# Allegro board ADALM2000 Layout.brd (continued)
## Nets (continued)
GND: A1.5 A2.5 A2.7 A2.15 A4.5 A6.4(V-) A6.PAD A7.PAD A8.4(V-) A8.PAD A9.PAD A11.3 A13.4(V-) A13.PAD A14.3 C1.2(N2) C2.1 C3.2(N2) C4.2(N2) C5.2(N2) C6.2(N2) C7.2(N2) C8.2(N2) C9.2(N2) C10.2(N2) C11.2(N2) C12.2(N2) C13.2(N2) C14.2(N2) C16.2(N2) C17.2(N2) C18.2(N2) C19.2(N2) C20.2(N2) C21.2(N2) C22.2(N2) C23.2(N2) C24.1 C25.2(N2) C26.2(N2) C27.2(N2) C28.2(N2) C29.2(N2) C30.2(N2) C31.2(N2) C32.2(N2) C33.2(N2) C34.2(N2) C35.2(N2) C36.2(N2) C37.2(N2) C38.2(N2) C39.2(N2) C40.2(N2) C41.2(N2) C42.2(N2) C43.2(N2) C44.2(N2) C45.2(N2) C46.2(N2) C47.2(N2) C48.2(N2) C49.2(N2) C50.2(N2) C51.2(N2) C53.2(N2) C54.2(N2) C55.2(N2) C56.2(N2) C57.2(N2) C58.2(N2) C59.2(N2) C60.2(N2) C61.2(N2) C62.2(N2) C63.2(N2) C64.2(N2) C65.2(N2) C66.2(N2) C67.2(N2) C68.2(N2) C69.2(N2) C70.2(N2) C71.2(N2) C74.2(N2) C77.2(N2) C78.2(N2) C79.2(N2) C80.2(N2) C81.2(N2) C82.2(N2) C83.2(N2) C84.2(N2) C86.2(N2) C87.2(N2) C90.2(N2) C91.2(N2) C93.2(N2) C96.2(N2) C97.2(N2) C98.2(N2) C99.2(N2) C100.2(N2) C101.2(N2) C102.2(N2) C105.2(N2) C106.1 C107.2(N2) C108.1 C109.2(N2) C110.1 C111.2(N2) C112.1 C113.2(N2) C114.1 C115.2(N2) C116.1 C117.2(N2) C118.1 C119.2(N2) C120.1 C121.1 C123.2(N2) C124.2(N2) C125.2(N2) C126.2(N2) C127.2(N2) C128.2(N2) C131.2(N2) C133.1 C134.2(N2) C135.2(N2) C136.2(N2) C137.2(N2) C138.2(N2) C139.2(N2) C140.2(N2) C141.2(N2) C142.2(N2) C144.2(N2) C148.2(N2) C149.2(N2) C150.2(N2) C151.2(N2) C152.2(N2) C153.2(N2) C154.2(N2) C155.1 C156.2(N2) C157.1 C158.2(N2) C159.1 C160.2(N2) C161.1 C164.2(N2) C165.1 C166.2(N2) C167.1 C168.2(N2) C169.1 C170.2(N2) C171.1 C172.1 C174.2(N2) C175.2(N2) C176.2(N2) C177.2(N2) C178.2(N2) C179.2(N2) C180.2(N2) C182.2(N2) C183.2(N2) C185.2(N2) C186.2(N2) C187.2(N2) C190.2(N2) C191.2(N2) C192.2(N2) C193.1 C194.1 C195.2(N2) C196.2(N2) C197.2(N2) C198.2(N2) C199.2(N2) C202.2(N2) C204.2(N2) C205.2(N2) C206.2(N2) C207.2(N2) C208.2(N2) C209.2(N2) C210.2(N2) C211.2(N2) C212.2(N2) C213.2(N2) C214.2(N2) C215.2(N2) C216.1 C217.2(N2) C218.2(N2) C219.2(N2) C220.2(N2) C221.2(N2) C222.2(N2) C223.2(N2) C224.2(N2) C225.2(N2) C226.2(N2) C227.2(N2) C228.2(N2) C229.2(N2) C230.2(N2) C231.2(N2) C232.2(N2) C233.2(N2) C234.2(N2) C235.2(N2) C238.2(N2) C239.2(N2) C240.2(N2) C241.2(N2) C242.2(N2) C243.1 C244.2(N2) C245.1 C246.2(N2) C247.1 C248.2(N2) C249.2(N2) C250.2(N2) C251.1 C253.2(N2) C254.1 C256.2(N2) C257.2(N2) C258.2(N2) C259.1 C260.2(N2) C261.2(N2) C262.2(N2) C263.1 C264.2(N2) C265.1 C268.2(N2) C269.1 C270.2(N2) C271.1 C272.2(N2) C273.1 C274.2(N2) C275.1 C276.2(N2) C277.1 C278.2(N2) C279.2(N2) C282.2(N2) C283.1 C284.2(N2) C285.2(N2) C286.2(N2) C287.2(N2) C288.2(N2) C289.2(N2) C290.2(N2) C291.2(N2) C292.2(N2) C293.2(N2) C294.2(N2) C295.2(N2) C296.2(N2) C297.2(N2) C298.2(N2) C299.2(N2) C300.2(N2) C301.2(N2) C308.2(N2) C309.1 C310.2(N2) C311.2(N2) C314.2(N2) C315.1 C316.2(N2) C317.1 C318.2(N2) C319.1 C320.2(N2) C321.2(N2) C322.2(N2) C323.1 C324.2(N2) C327.2(N2) C328.2(N2) C329.2(N2) C330.2(N2) C331.2(N2) C332.2(N2) C333.2(N2) C334.2(N2) C335.2(N2) C336.2(N2) C338.2(N2) C340.2(N2) C579.2(N2) C588.2(N2) C589.2(N2) C595.2(N2) C596.2(N2) C597.2(N2) C598.2(N2) C599.2(N2) C600.2(N2) C607.2(N2) C614.2(N2) C615.2(N2) C616.2(N2) C617.2(N2) C618.2(N2) C626.2(N2) C633.2(N2) C637.2(N2) C639.2(N2) C641.2(N2) C643.2(N2) C644.2(N2) C645.2(N2) C647.2(N2) C648.1 C649.2(N2) C650.1 C651.2(N2) C652.2(N2) C654.2(N2) C655.2(N2) C656.2(N2) C657.2(N2) C658.2(N2) C659.2(N2) C660.2(N2) C662.2(N2) C663.2(N2) C664.2(N2) C665.2(N2) C666.2(N2) C667.2(N2) C668.2(N2) C669.2(N2) C670.2(N2) C671.2(N2) C672.2(N2) C673.2(N2) C674.2(N2) C675.2(N2) C676.2(N2) C678.2(N2) C679.2(N2) C680.2(N2) C683.2(N2) C686.2(N2) C692.1 C696.2(N2) C697.2(N2) C698.2(N2) C699.2(N2) C700.2(N2) C701.2(N2) C702.2(N2) C703.2(N2) C704.2(N2) C705.2(N2) C706.2(N2) C707.2(N2) C708.2(N2) C709.2(N2) C710.2(N2) C711.2(N2) C712.2(N2) C713.2(N2) C737.2(N2) C738.2(N2) C740.2(N2) C742.2(N2) C745.1 C746.1 C748.2(N2) C751.1 C753.1 C754.2(N2) C756.1 C758.2(N2) C761.2(N2) C762.2(N2) C769.2(N2) C774.2(N2) C788.2(N2) C789.2(N2) C790.2(N2) C792.2(N2) C793.2(N2) C795.1 C801.2(N2) C803.2(N2) C805.2(N2) C807.2(N2) D1.A(P) D2.1(P) D3.1(P) D4.1(P) D5.1(P) D6.1(P) D7.1(P) D8.1(P) D9.1(P) D10.1(P) D11.1(P) D12.1(P) D13.1(P) D14.1(P) D15.1(P) D16.1(P) D17.1(P) D18.1(P) D19.1(P) D26.C D739.A(P) D741.A(P) E687.1 GND_4.1(N1) GND_5.1(N1) GND_6.1(N1) GND_7.1(N1) GND_8.1(N1) GND_9.1(N1) GND_10.1(N1) L2.1 L10.3 L13.1 L14.1 P1.5 P1.6 P1.11 P1.12 P510.7 P510.9 Q2.2(S) Q3.1 Q4.1 Q5.1 Q8.2(S) Q9.2(S) Q512.2(S) R2.2(N2) R4.2(N2) R8.2(N2) R12.2(N2) R13.2(N2) R18.2(N2) R21.2(N2) R31.1 R43.2(N2) R46.2(N2) R57.1 R67.2(N2) R69.2(N2) R70.2(N2) R74.1 R75.1 R77.1 R80.2(N2) R82.2(N2) R83.1 R84.1 R85.1 R92.2(N2) R93.2(N2) R94.2(N2) R105.2(N2) R106.2(N2) R116.2(N2) R117.1 R120.2(N2) R121.1 R122.1 R123.1 R124.1 R138.2(N2) R141.2(N2) R154.2(N2) R158.1 R165.2(N2) R197.2(N2) R198.2(N2) R199.2(N2) R200.2(N2) R203.2(N2) R204.2(N2) R206.2(N2) R208.2(N2) R213.2(N2) R214.2(N2) R583.2(N2) R587.2(N2) R590.2(N2) R593.2(N2) R594.2(N2) R634.2(N2) R636.2(N2) R661.2(N2) R743.1 R747.2(N2) R760.1 R764.2(N2) R766.1 R800.2(N2) S1.3 S1.4 TP5.1(N1) TP6.1(N1) TP7.1(N1) U2.5 U2.11 U2.14 U2.19 U2.34 U2.62 U2.64 U2.PAD U6.1 U6.19 U6.20 U6.21 U6.22 U6.PAD U7.4 U7.8 U7.PAD U8.10 U8.12 U9.10 U9.12 U10.4 U10.10 U10.14 U10.15 U10.16 U10.PAD U11.8 U11.12 U12.4 U12.5 U12.PAD U13.6 U14.1 U14.3 U14.8 U14.11 U14.15 U14.22 U14.PAD U15.PAD U17.2 U18.1 U18.2 U19.1 U19.2 U20.3 U508.B3 U509.4 U509.8 U509.PAD U511.A1 U511.A11 U511.B8 U511.C5 U511.C15 U511.D2 U511.D12 U511.E5 U511.E7 U511.E8 U511.E9 U511.F10 U511.G3 U511.G5 U511.G13 U511.H6 U511.H8 U511.H10 U511.J5 U511.J9 U511.K4 U511.K7 U511.K10 U511.K14 U511.L1 U511.L5 U511.L11 U511.M8 U511.N5 U511.N15 U511.P2 U511.P12 U511.R9 U518.1 U518.19 U518.20 U518.21 U518.22 U518.PAD U524.PAD U646.A9 U646.B1 U646.B3 U646.B9 U646.D1 U646.D8 U646.E1 U646.E2 U646.E8 U646.F9 U646.G1 U646.G8 U646.G9 U646.J2 U646.J8 U646.M1 U646.M9 U646.P1 U646.P9 U646.T1 U646.T9 VR1.1 Y1.2 Y523.2 Y578.2
PGND: C280.2(N2) C281.2(N2) C312.2(N2) C313.2(N2) C325.2(N2) C326.2(N2) L10.4(N4) P516.5 P519.5 R190.2(N2) R191.1 R192.2(N2) R744.2(N2) R749.2(N2) U16.B2 U21.PAD
VCCPINT: C279.1 C663.1 C665.1 C667.1 C669.1 C670.1 C671.1 C672.1 C673.1 C674.1 E26.2(N2) U511.E10 U511.F9 U511.G6 U511.G10 U511.H5 U511.J10 U511.K5 U511.L10 VCCPINT.1(N1)
VCCPLL: C680.1 C686.1 E677.2(N2) U511.F5(VCCPLL)
VIN: C4.1 C178.1 C183.1 C187.1 C190.1 C320.1 C321.1 C648.2(N2) C737.1 C738.1 C740.1 C742.1 DS11.A(P) DS12.A(P) E4.1 L10.2 R3.1 R88.1 R517.1 R638.1 R640.1 R750.2(N2) U6.14 U6.15 U6.16(VIN6) U6.25 U6.26 U6.27 U509.10 U518.14 U518.15 U518.16(VIN6) U518.25 U518.26 U518.27 VIN.1(N1)
VIN_5V_USB_DATA: C325.1 F1.2(N2) P516.1 R156.2(N2) U21.7 U21.8
VIN_5V_USB_POWER: C326.1 P519.1 R166.1 U16.A1 U21.1 U21.2
20MHZ_REFCLK: C52.2(N2) U14.16
AD9963_CSN: U2.17 U511.E11
AD9963_RESETN: R14.2(N2) U2.15 U511.E12
ADC_SC1_N: C122.2(N2) C123.1 D21.3 R38.2(N2) U2.4
ADC_SC1_P: C121.2(N2) C122.1 D20.3 R37.2(N2) U2.3
ADC_SC2_N: C172.2(N2) C173.1 D22.3 R63.2(N2) U2.12
ADC_SC2_P: C173.2(N2) C174.1 D23.3 R64.2(N2) U2.13
ADF4360_CS: U14.19 U511.G15
ADF4360_LD: U14.23 U15.10
ADP2114_VIN_1: C748.1 R517.2(N2) U518.4 U518.8 U518.10 U518.31
ADP2114_VIN_2: C196.1 R88.2(N2) R89.1 R91.2(N2) R149.2(N2) U6.4 U6.8 U6.28
AWG1_PD: A7.1 Q8.3 R201.2(N2)
AWG2_PD: A9.1 Q9.3 R202.2(N2)
CALIB_REFERENCE1: C219.1 CALIB_REF1.1(N1) R79.2(N2) R80.1 U8.4 U9.4
CALIB_REFERENCE2: C220.1 CALIB_REF2.1(N1) R81.2(N2) R82.1 U8.9 U9.9
COMP_1P35V: C756.2(N2) C757.1 U518.7
COMP_1V0_D: C197.1 R90.1 U6.2
COMP_1V8: C751.2(N2) R752.1 U518.2
COMP_3V3_D: C199.1 C203.1 U6.7
DAC_AVG1_N: A10.2 C252.1 R95.1 U2.66
DAC_AVG1_P: A10.3 C248.1 R93.1 U2.65
DAC_AVG2_N: A10.6 C255.1 R96.1 U2.59
DAC_AVG2_P: A10.5 C249.1 R94.1 U2.60
DAC_OFFSET_SC1: A6.3 U11.5
DAC_OFFSET_SC2: A6.5 U11.10
DAC_USR_POW_NEG: R151.2(N2) R153.1 R159.1
DAC_USR_POW_NEG_9963: R153.2(N2) U2.69
DAC_USR_POW_POS: A12.3 R150.2(N2) R152.1
DAC_USR_POW_POS_9963: R152.2(N2) U2.68
DDR3_A0: R601.1 U511.P1 U646.N3
DDR3_A1: R608.1 U511.N1 U646.P7
DDR3_A2: R602.1 U511.M1 U646.P3
DDR3_A3: R609.1 U511.M4 U646.N2
DDR3_A4: R603.1 U511.P3 U646.P8
DDR3_A5: R610.1 U511.P4 U646.P2
DDR3_A6: R604.1 U511.P5 U646.R8
DDR3_A7: R611.1 U511.M5 U646.R2
DDR3_A8: R605.1 U511.P6 U646.T8
DDR3_A9: R612.1 U511.N4 U646.R3
DDR3_A10: R606.1 U511.J1 U646.L7
DDR3_A11: R613.1 U511.L2 U646.R7
DDR3_A12: R620.1 U511.M2 U646.N7
DDR3_A13: R627.1 U511.K2 U646.T3
DDR3_A14: R619.1 U511.K1 U646.T7
DDR3_BA0: R628.1 U511.M6 U646.M2
DDR3_BA1: R621.1 U511.R1 U646.N8
DDR3_BA2: R629.1 U511.N6 U646.M3
DDR3_CAS#: R623.1 U511.R5 U646.K3
DDR3_CK_N: R625.2(N2) U511.N2 U646.K7
DDR3_CK_P: R625.1 U511.N3 U646.J7
DDR3_CKE: R631.1 U511.L3 U646.K9
DDR3_CS#: R632.1 U511.R2 U646.L2
DDR3_DM0: U511.B1 U646.E7
DDR3_DM1: U511.D3 U646.D3
DDR3_DQ0: U511.D4 U646.E3
DDR3_DQ1: U511.A2 U646.F7
DDR3_DQ2: U511.C4 U646.F2
DDR3_DQ3: U511.C1 U646.F8
DDR3_DQ4: U511.B4 U646.H3
DDR3_DQ5: U511.A4 U646.H8
DDR3_DQ6: U511.C3 U646.G2
DDR3_DQ7: U511.A3 U646.H7
DDR3_DQ8: U511.E1 U646.D7
DDR3_DQ9: U511.D1 U646.C3
DDR3_DQ10: U511.E2 U646.C8
DDR3_DQ11: U511.E3 U646.C2
DDR3_DQ12: U511.F3 U646.A7
DDR3_DQ13: U511.G1 U646.A2
DDR3_DQ14: U511.H1 U646.B8
DDR3_DQ15: U511.H2 U646.A3
DDR3_DQS0_N: U511.B2 U646.G3
DDR3_DQS0_P: U511.C2 U646.F3
DDR3_DQS1_N: U511.F2 U646.B7
DDR3_DQS1_P: U511.G2 U646.C7
DDR3_ODT: R624.1 U511.K3 U646.K1
DDR3_RAS#: R630.1 U511.R6 U646.J3
DDR3_RST#: R636.1 U511.L4 U646.T2
DDR3_WE#: R622.1 U511.R3 U646.L3
DIO_0: D18.3 RT11.2(N2) U511.K11
DIO_1: D17.3 RT12.2(N2) U511.K12
DIO_2: D16.3 RT13.2(N2) U511.K13
DIO_3: D15.3 RT14.2(N2) U511.L13
DIO_4: D14.3 RT15.2(N2) U511.L14
DIO_5: D13.3 RT16.2(N2) U511.M14
DIO_6: D12.3 RT17.2(N2) U511.L15
DIO_7: D11.3 RT18.2(N2) U511.M15
DIO_8: D3.3 RT2.1 U511.N13
DIO_9: D4.3 RT3.1 U511.P14
DIO_10: D5.3 RT4.1 U511.R12
DIO_11: D6.3 RT5.1 U511.R13
DIO_12: D7.3 RT6.1 U511.P11
DIO_13: D8.3 RT7.1 U511.R11
DIO_14: D9.3 RT8.1 U511.P15
DIO_15: D10.3 RT9.1 U511.R15
DONE_LED_OVERRIDE: Q1.1 R130.2(N2) U15.4
EN_AWG1: Q8.1 R199.1 U15.16
EN_AWG2: Q9.1 R200.1 U15.15
EN_DAT_USB: R189.2(N2) R190.1 U21.6
EN_POW_USB: R166.2(N2) R189.1 U21.3
EN_SC: Q3.2(S) R154.1 U15.3 U17.3(SHDN_N) VR1.4(SHDN_N)
EN_SC1_CAL2: A2.8 U15.7
EN_SC1_HG: A4.1 A4.9 U15.12
EN_SC1_LG: A4.8 A4.16 U15.11
EN_SC2_CAL2: A2.16 U15.8
EN_SC2_HG: A1.1 A1.9 U15.14
EN_SC2_LG: A1.8 A1.16 U15.13
EN_SC_CAL1: A2.1 A2.9 U15.9
EN_USR_POW_NEG: Q5.2(S) U15.2
EN_USR_POW_POS: Q4.2(S) U15.1
ENABLE_POW_NEG: A14.5 Q5.3 R147.1
ENABLE_POW_POS: A12.5 Q4.3 R129.1
FB_1V0_D: R207.2(N2) R208.1 U6.32
FB_1V8: R765.1 R766.2(N2) U518.32
FB_1V35: R763.2(N2) R764.1 U518.9
FB_3V3_D: R205.2(N2) R206.1 U6.9
IN_SC1_N: C72.1 P1.1 R16.1
IN_SC1_P: C75.1 P1.2 R19.1
IN_SC2_N: C129.1 P1.3 R41.1
IN_SC2_P: C132.1 P1.4 R44.1
JTAG_TCK: P510.4 TCK.1(N1) U511.G9
JTAG_TDI: P510.8 TDI.1(N1) U511.L7
JTAG_TDO: P510.6 TDO.1(N1) U511.L8
JTAG_TMS: P510.2 TMS.1(N1) U511.L9
LOOP_FILT: C223.1 R6.1 R86.1 U14.24
MASTER_CLK_N: C237.2(N2) U2.56
MASTER_CLK_P: C236.2(N2) U2.57
MUX_EN: R47.2(N2) U8.16 U9.16
OFFSET_AWG1: R99.1 U11.4
OFFSET_AWG2: R100.1 U11.11
OFFSET_SC1: A6.1 C304.2(N2) OFF_SC1.1(N1) R29.1 R127.2(N2)
OFFSET_SC2: A6.7 C305.2(N2) OFF_SC2.1(N1) R54.1 R128.2(N2)
OUT_AWG1: P1.10 R132.2(N2) R135.1
OUT_AWG1_CALIB: R135.2(N2) R197.1 U8.3
OUT_AWG2: P1.9 R133.2(N2) R134.1
OUT_AWG2_CALIB: R134.2(N2) R198.1 U9.3
PG_1P0V: R89.2(N2) U6.29 U518.28
PG_1P8V: R750.1 U6.13 U7.3 U10.6 U12.3 U518.13 U518.29
PS-SRST#: R791.2(N2) U508.A4 U511.B11
PS_MIO01_500_QSPI0_SS_B: R586.2(N2) U508.C2 U511.A5
PS_MIO02_500_QSPI0_IO0: R593.1 U508.D3 U511.A8
PS_MIO03_500_QSPI0_IO1: R594.1 U508.D2 U511.A7
PS_MIO04_500_QSPI0_IO2: R590.1 U508.C4(W#DQ2) U511.C8
PS_MIO05_500_QSPI0_IO3: IO3.1(N1) P510.5 R591.1 U508.D4 U511.A9
PS_MIO06_500_QSPI0_SCLK: R583.1 U508.B2 U511.A10
PS_MIO07_500_USB_RESET_B: R798.2(N2) U511.A12 U524.27
PS_MIO28_501_USB0_D4: U511.A15 U524.7
PS_MIO29_501_USB0_DIR: U511.D11 U524.31
PS_MIO30_501_USB0_STP: U511.B15 U524.29
PS_MIO31_501_USB0_NXT: U511.C12 U524.2
PS_MIO32_501_USB0_D0: U511.E15 U524.3
PS_MIO33_501_USB0_D1: U511.C11 U524.4
PS_MIO34_501_USB0_D2: U511.D15 U524.5
PS_MIO35_501_USB0_D3: U511.A14 U524.6
PS_MIO36_501_USB0_CLK: U511.B14 U524.1
PS_MIO37_501_USB0_D5: U511.C14 U524.9
PS_MIO38_501_USB0_D6: U511.A13 U524.10
PS_MIO39_501_USB0_D7: U511.D14 U524.13
PWR_GD_1.35V: C588.1 R585.2(N2) R587.1 U511.C9 U518.12
PWR_GOOD: R155.2(N2) U6.12 U7.6 U10.3 U15.19
REF_1V0_AWG: C62.1 R143.2(N2) U2.63
REF_1V2: A8.3 A8.5 A13.3 A13.5 C97.1 C291.1 C293.1 C296.1 U11.7(VREF) U19.5(VOUT_SENSE) U19.6 U20.10(VREFIN)
REF_1V2_SC: C289.1 C292.1 R79.1 R81.1 R115.1 U18.5(VOUT_SENSE) U18.6
REF_AWG1: A13.1 A13.2 R97.1
REF_AWG2: A13.6 A13.7 R98.1
REF_SC1: A8.7 C302.2(N2) R28.1 R125.2(N2)
REF_SC2: A8.1 C303.2(N2) R55.1 R126.2(N2)
RX_CLK: R173.1 U511.N11
RXCML: C65.1 R36.2(N2) R62.2(N2) U2.10
RXD_0: R188.2(N2) U511.P10
RXD_1: R187.2(N2) U511.R10
RXD_2: R186.2(N2) U511.P8
RXD_3: R185.2(N2) U511.P9
RXD_4: R184.2(N2) U511.N7
RXD_5: R183.2(N2) U511.N8
RXD_6: R182.2(N2) U511.M10
RXD_7: R181.2(N2) U511.M11
RXD_8: R180.2(N2) U511.R7
RXD_9: R179.2(N2) U511.R8
RXD_10: R178.2(N2) U511.M9
RXD_11: R177.2(N2) U511.N9
RXIQ: R176.2(N2) U511.P13
SC_CAL_MUX0: U8.15 U9.15 U15.6
SC_CAL_MUX1: U8.14 U9.14 U15.5
SC_PD: Q3.3 R131.1 U3.14 U3.20 U4.14 U4.20
SCL: R211.2(N2) U11.14 U15.23 U20.7 U511.F14
SCLK: U2.16 U14.17 U511.E13
SDA: R210.2(N2) U11.13 U15.22 U20.8 U511.F13
SDIO: U2.18 U14.18 U511.F12
STAT_DATA: R196.2(N2) U15.21 U21.11
STAT_POWER: R195.2(N2) U15.20 U21.14
SUPPLY_NEG: C308.1 P1.7 R139.1 R160.2(N2) R163.2(N2)
SUPPLY_NEG_MONITOR: A11.1 R136.2(N2) U2.71
SUPPLY_POS: C297.1 P1.8 R137.1 R161.2(N2) R162.2(N2)
SUPPLY_POS_MONITOR: R137.2(N2) R138.1 U2.70
TRIG_1: D19.3 RT10.2(N2) U511.M12
TRIG_2: D2.3 RT1.1 U511.N12
TX_CLK: R174.2(N2) U511.L12
TXD_0: R171.1 U511.H12
TXD_1: R172.1 U511.G11
TXD_2: R170.1 U511.H13
TXD_3: R169.1 U511.G12
TXD_4: R168.1 U511.H14
TXD_5: R167.1 R217.2(N2) U511.G14
TXD_6: R114.1 U511.K15
TXD_7: R113.1 U511.J15
TXD_8: R112.1 U511.J14
TXD_9: R109.1 U511.J13
TXD_10: R111.1 U511.J11
TXD_11: R110.1 U511.H11
TXIQ: R175.2(N2) U511.N14
UART_RX: P510.1 RX.1(N1) U511.C6
UART_TX: P510.3 TX.1(N1) U511.B7
UNNAMED_16_ADP5074_I189_COMP: C182.1 R1.2(N2) U10.7
UNNAMED_16_ADP5074_I189_FB: R7.2(N2) R10.1 U10.8
UNNAMED_16_ADP5074_I189_SLEW: R8.1 U10.2
UNNAMED_16_ADP5074_I189_SS: R2.1 U10.5
UNNAMED_16_ADP5074_I189_SW: D24.C L2.2(N2) U10.1
UNNAMED_16_ADP5074_I189_VREF: C6.1 R7.1 U10.9
UNNAMED_16_ADP5074_I189_VREG: C3.1 U10.11(VREG)
UNNAMED_16_ADP7182V2_I221_ADJ: R77.2(N2) R78.1 U13.3
UNNAMED_16_ADP7182V2_I221_VOUT: C218.1 E19.1 R78.2(N2) U13.1 U13.2(VOUT1)
UNNAMED_16_CAP_I180_N1: C1.1 R1.1
UNNAMED_16_CAP_I199_N1: C8.1 D24.A(P) L4.1 R9.1
UNNAMED_16_CAP_I236_N1: C328.1 VR1.3
UNNAMED_29_CN30PODDEVENV2_I44_1: P1.16 RT11.1
UNNAMED_29_CN30PODDEVENV2_I44_2: P1.18(N9) RT12.1
UNNAMED_29_CN30PODDEVENV2_I44_3: P1.20 RT13.1
UNNAMED_29_CN30PODDEVENV2_I44_4: P1.22 RT14.1
UNNAMED_29_CN30PODDEVENV2_I44_5: P1.24 RT15.1
UNNAMED_29_CN30PODDEVENV2_I44_6: P1.26 RT16.1
UNNAMED_29_CN30PODDEVENV2_I44_7: P1.28 RT17.1
UNNAMED_29_CN30PODDEVENV2_I44_8: P1.30 RT18.1
UNNAMED_29_CN30PODDEVENV2_I44_N: P1.14 RT10.1
UNNAMED_29_CN30PODDEVENV2_I45_1: P1.15 RT2.2(N2)
UNNAMED_29_CN30PODDEVENV2_I45_2: P1.17 RT3.2(N2)
UNNAMED_29_CN30PODDEVENV2_I45_3: P1.19 RT4.2(N2)
UNNAMED_29_CN30PODDEVENV2_I45_4: P1.21 RT5.2(N2)
UNNAMED_29_CN30PODDEVENV2_I45_5: P1.23 RT6.2(N2)
UNNAMED_29_CN30PODDEVENV2_I45_6: P1.25 RT7.2(N2)
UNNAMED_29_CN30PODDEVENV2_I45_7: P1.27 RT8.2(N2)
UNNAMED_29_CN30PODDEVENV2_I45_8: P1.29 RT9.2(N2)
UNNAMED_29_CN30PODDEVENV2_I45_N: P1.13 RT1.2(N2)
UNNAMED_30_AD9963_I47_AUXADCREF: C63.1 U2.2
UNNAMED_30_AD9963_I47_AUXIN1: R3.2(N2) R4.1 U2.72
UNNAMED_30_AD9963_I47_DLLFILT: C64.1 R15.1 U2.54
UNNAMED_30_AD9963_I47_RXBIAS: R13.1 U2.6
UNNAMED_30_AD9963_I47_TRXCLK: R173.2(N2) U2.36
UNNAMED_30_AD9963_I47_TRXD0: R188.1 U2.32
UNNAMED_30_AD9963_I47_TRXD1: R187.1 U2.31
UNNAMED_30_AD9963_I47_TRXD2: R186.1 U2.30
UNNAMED_30_AD9963_I47_TRXD3: R185.1 U2.29
UNNAMED_30_AD9963_I47_TRXD4: R184.1 U2.28
UNNAMED_30_AD9963_I47_TRXD5: R183.1 U2.27
UNNAMED_30_AD9963_I47_TRXD6: R182.1 U2.26
UNNAMED_30_AD9963_I47_TRXD7: R181.1 U2.25
UNNAMED_30_AD9963_I47_TRXD8: R180.1 U2.24
UNNAMED_30_AD9963_I47_TRXD9: R179.1 U2.23
UNNAMED_30_AD9963_I47_TRXD10: R178.1 U2.22
UNNAMED_30_AD9963_I47_TRXD11: R177.1 U2.21
UNNAMED_30_AD9963_I47_TRXIQ: R176.1 U2.35
UNNAMED_30_AD9963_I47_TXCLK: R174.1 U2.37
UNNAMED_30_AD9963_I47_TXD0: R171.2(N2) U2.50
UNNAMED_30_AD9963_I47_TXD1: R172.2(N2) U2.49
UNNAMED_30_AD9963_I47_TXD2: R170.2(N2) U2.48
UNNAMED_30_AD9963_I47_TXD3: R169.2(N2) U2.47
UNNAMED_30_AD9963_I47_TXD4: R168.2(N2) U2.46
UNNAMED_30_AD9963_I47_TXD5: R167.2(N2) U2.45
UNNAMED_30_AD9963_I47_TXD6: R114.2(N2) U2.44
UNNAMED_30_AD9963_I47_TXD7: R113.2(N2) U2.43
UNNAMED_30_AD9963_I47_TXD8: R112.2(N2) U2.42
UNNAMED_30_AD9963_I47_TXD9: R109.2(N2) U2.41
UNNAMED_30_AD9963_I47_TXD10: R111.2(N2) U2.40
UNNAMED_30_AD9963_I47_TXD11: R110.2(N2) U2.39
UNNAMED_30_AD9963_I47_TXIQ: R175.1 U2.38
UNNAMED_30_CAP_I112_N1: C66.1 R15.2(N2)
UNNAMED_31_AD8066_I6_INV: A3.2 C89.1 R24.1
UNNAMED_31_AD8066_I6_NINV: A3.3 C85.2(N2) R22.2(N2)
UNNAMED_31_AD8066_I6_OUT: A3.1 C89.2(N2) R24.2(N2) R26.1
UNNAMED_31_AD8066_I55_INV: A3.6 C92.1 R25.1
UNNAMED_31_AD8066_I55_NINV: A3.5 C88.2(N2) R23.2(N2)
UNNAMED_31_AD8066_I55_OUT: A3.7(OUT) C92.2(N2) R25.2(N2) R27.1
UNNAMED_31_ADA49402V2_I232_: C103.2(N2) R34.2(N2) U3.23
UNNAMED_31_ADA49402V2_I232__1: C104.1 R27.2(N2) R28.2(N2) R35.1 U3.1
UNNAMED_31_ADA49402V2_I232__2: C104.2(N2) R35.2(N2) U3.2
UNNAMED_31_ADA49402V2_I232__3: C103.1 R26.2(N2) R29.2(N2) R34.1 U3.24
UNNAMED_31_ADA49402V2_I232__4: R37.1 U3.19
UNNAMED_31_ADA49402V2_I232__5: R38.1 U3.18
UNNAMED_31_ADA49402V2_I232_VOCM: R36.1 U3.11 U3.17
UNNAMED_31_ADA49402V2_I233_: R33.2(N2) U3.8
UNNAMED_31_ADA49402V2_I233__1: R39.1 U3.13
UNNAMED_31_ADA49402V2_I233__2: R40.1 U3.12
UNNAMED_31_ADA49402V2_I233__3: R32.2(N2) U3.5
UNNAMED_31_ADA49402V2_I233__4: R31.2(N2) R33.1 U3.7
UNNAMED_31_ADA49402V2_I233__5: R30.2(N2) R32.1 U3.6
UNNAMED_31_ADG202N_I1_D: A2.6 A4.10 A4.15 C88.1 R23.1
UNNAMED_31_ADG202N_I1_S: A4.14 C73.2(N2) C74.1 C181.2(N2) C185.1 R17.2(N2) R18.1
UNNAMED_31_ADG202N_I2_S: A4.11 C69.1 C72.2(N2) C73.1 C181.1 R16.2(N2) R17.1
UNNAMED_31_ADG202N_I19_D: A2.3 A4.2 A4.7 C85.1 R22.1
UNNAMED_31_ADG202N_I19_S: A4.3 C71.1 C75.2(N2) C76.1 C189.1 R19.2(N2) R20.1
UNNAMED_31_ADG202N_I20_S: A4.6 C76.2(N2) C77.1 C189.2(N2) C336.1 R20.2(N2) R21.1
UNNAMED_31_ADG1404V2_I235_D: A2.2 U8.6
UNNAMED_31_DIO3PV3_I80_N: D20.2 D21.2 R40.2(N2)
UNNAMED_31_DIO3PV3_I80_P: D20.1(P) D21.1(P) R39.2(N2)
UNNAMED_32_AD8066_I42_INV: A5.6 C146.1 R50.1
UNNAMED_32_AD8066_I42_NINV: A5.5 C143.2(N2) R48.2(N2)
UNNAMED_32_AD8066_I42_OUT: A5.7(OUT) C146.2(N2) R50.2(N2) R53.1
UNNAMED_32_AD8066_I82_INV: A5.2 C147.1 R51.1
UNNAMED_32_AD8066_I82_NINV: A5.3 C145.2(N2) R49.2(N2)
UNNAMED_32_AD8066_I82_OUT: A5.1 C147.2(N2) R51.2(N2) R52.1
UNNAMED_32_ADA49402V2_I190_: C163.2(N2) R61.2(N2) U4.2
UNNAMED_32_ADA49402V2_I190__1: C162.1 R52.2(N2) R55.2(N2) R60.1 U4.24
UNNAMED_32_ADA49402V2_I190__2: C163.1 R53.2(N2) R54.2(N2) R61.1 U4.1
UNNAMED_32_ADA49402V2_I190__3: C162.2(N2) R60.2(N2) U4.23
UNNAMED_32_ADA49402V2_I190__4: R63.1 U4.19
UNNAMED_32_ADA49402V2_I190__5: R64.1 U4.18
UNNAMED_32_ADA49402V2_I190_VOCM: R62.1 U4.11 U4.17
UNNAMED_32_ADA49402V2_I191_: R59.2(N2) U4.8
UNNAMED_32_ADA49402V2_I191__1: R66.1 U4.12
UNNAMED_32_ADA49402V2_I191__2: R65.1 U4.13
UNNAMED_32_ADA49402V2_I191__3: R58.2(N2) U4.5
UNNAMED_32_ADA49402V2_I191__4: R57.2(N2) R59.1 U4.7
UNNAMED_32_ADA49402V2_I191__5: R56.2(N2) R58.1 U4.6
UNNAMED_32_ADG202N_I18_S: A1.14 C130.2(N2) C134.1 C339.2(N2) C340.1 R45.2(N2) R46.1
UNNAMED_32_ADG202N_I25_S: A1.11 C128.1 C130.1 C132.2(N2) C339.1 R44.2(N2) R45.1
UNNAMED_32_ADG202N_I26_S: A1.6 C95.2(N2) C131.1 C337.2(N2) C338.1 R42.2(N2) R43.1
UNNAMED_32_ADG202N_I34_S: A1.3 C95.1 C126.1 C129.2(N2) C337.1 R41.2(N2) R42.1
UNNAMED_32_ADG202N_I163_S: A1.2 A1.7 A2.14 C145.1 R49.1
UNNAMED_32_ADG202N_I164_S: A1.10 A1.15 A2.11 C143.1 R48.1
UNNAMED_32_ADG1404V2_I201_D: A2.10 U9.6
UNNAMED_32_DIO3PV3_I76_N: D22.2 D23.2 R66.2(N2)
UNNAMED_32_DIO3PV3_I76_P: D22.1(P) D23.1(P) R65.2(N2)
UNNAMED_33_AD8000_I139_FB: A7.2 R107.2(N2) R194.2(N2)
UNNAMED_33_AD8000_I139_INV: A7.3 C266.1 R101.2(N2) R102.2(N2) R107.1
UNNAMED_33_AD8000_I139_NINV: A7.4 C260.1 R99.2(N2) R105.1
UNNAMED_33_AD8000_I139_OUT: A7.7 R132.1
UNNAMED_33_AD8000_I141_FB: A9.2 R108.2(N2) R193.2(N2)
UNNAMED_33_AD8000_I141_INV: A9.3 C267.1 R103.2(N2) R104.2(N2) R108.1
UNNAMED_33_AD8000_I141_NINV: A9.4 C261.1 R100.2(N2) R106.1
UNNAMED_33_AD8000_I141_OUT: A9.7 R133.1
UNNAMED_33_ADOPAMP2_I1_OUT: A10.1 C252.2(N2) R95.2(N2) R102.1
UNNAMED_33_ADOPAMP2_I101_OUT: A10.7 C255.2(N2) R96.2(N2) R104.1
UNNAMED_33_CAP_I33_N1: C256.1 R97.2(N2) R101.1
UNNAMED_33_CAP_I95_N1: C257.1 R98.2(N2) R103.1
UNNAMED_33_CAP_I123_N2: C267.2(N2) R193.1
UNNAMED_33_CAP_I124_N2: C266.2(N2) R194.1
UNNAMED_34_AD56X5_I239_ADDR1: R119.2(N2) R120.1 U11.2
UNNAMED_34_AD56X5_I239_CLRN: R144.2(N2) U11.1 U11.6 U11.9
UNNAMED_34_AD56X7_I238_ADDR: R140.2(N2) R141.1 U20.6
UNNAMED_34_AD56X7_I238_CLRN: R142.2(N2) U20.4 U20.5
UNNAMED_34_AD56X7_I238_VOUTA: R150.1 U20.1
UNNAMED_34_AD56X7_I238_VOUTB: R151.1 U20.2
UNNAMED_34_AD8657V2_I252_: A6.2 C304.1 R123.2(N2) R127.1
UNNAMED_34_AD8657V2_I253_: A8.6 C302.1 R121.2(N2) R125.1
UNNAMED_34_AD8657V2_I254_: A8.2 C303.1 R122.2(N2) R126.1
UNNAMED_34_AD8657V2_I255_: A6.6 C305.1 R124.2(N2) R128.1
UNNAMED_34_AD8657V2_I284_: A11.6 C94.1 R117.2(N2) R118.1
UNNAMED_34_AD8657V2_I284__1: A11.5 C56.1 R115.2(N2) R116.1
UNNAMED_34_AD8657V2_I284_OUT: A11.7 C94.2(N2) R118.2(N2) R143.1
UNNAMED_35_AD8657V2_I160_: A11.2 R136.1 R139.2(N2)
UNNAMED_35_ADA48051_I114_: A14.4 C200.1 R159.2(N2) R160.1
UNNAMED_35_ADA48051_I114_VOUT: A14.1(VOUT) C179.1 C200.2(N2) D26.A(P) R163.1
UNNAMED_35_ADA48051_I125_: A12.4 C201.1 R158.2(N2) R161.1
UNNAMED_35_ADA48051_I125_VOUT: A12.1(VOUT) C175.1 C201.2(N2) D1.C R162.1
UNNAMED_35_CAP_I76_N2: C306.2(N2) C307.1
UNNAMED_36_ADF43609_I40_CC: C227.1 U14.12
UNNAMED_36_ADF43609_I40_CN: C230.1 U14.14
UNNAMED_36_ADF43609_I40_L1: L13.2(N2) R83.2(N2) U14.9
UNNAMED_36_ADF43609_I40_L2: L14.2(N2) R84.2(N2) U14.10
UNNAMED_36_ADF43609_I40_RFOUTA: C236.1 L15.1 U14.4
UNNAMED_36_ADF43609_I40_RFOUTB: C237.1 L16.1 U14.5
UNNAMED_36_ADF43609_I40_RSET: R85.2(N2) U14.13
UNNAMED_36_CAP_I47_N1: C52.1 Y1.3
UNNAMED_36_CAP_I53_N1: C238.1 R6.2(N2)
UNNAMED_37_ADP237X_I231_FB: C184.1 R70.1 R72.1 U7.5
UNNAMED_37_ADP237X_I231_SW: L3.1 U7.7
UNNAMED_37_ADP1614_I262_CLRES: R11.2(N2) R12.1 U12.9
UNNAMED_37_ADP1614_I262_COMP: C15.1 C17.1 U12.1
UNNAMED_37_ADP1614_I262_FB: R69.1 R73.1 U12.2
UNNAMED_37_ADP1614_I262_SS: C13.1 U12.10
UNNAMED_37_ADP1614_I262_SW1: D25.A(P) L6.2(N2) U12.6 U12.7
UNNAMED_37_ADP1614_I262_VIN: C16.1 R11.1 R68.1 U12.8(VIN)
UNNAMED_37_CAP_I212_N1: C191.1 C192.1 C195.1 C198.1 E8.1 L5.2(N2) R71.2(N2)
UNNAMED_37_CAP_I222_N1: C184.2(N2) C188.1 R71.1 R72.2(N2)
UNNAMED_37_CAP_I222_N2: C186.1 C188.2(N2) L3.2(N2) L5.1
UNNAMED_37_CAP_I260_N2: C15.2(N2) R67.1
UNNAMED_37_CAP_I315_N1: C23.1 D25.C L7.1
UNNAMED_37_LINLT1761_I320_ADJ: R164.2(N2) R165.1 U17.4
UNNAMED_38_ADP2114_I358_FREQ: R743.2(N2) U518.3
UNNAMED_38_ADP2114_I358_OPCFG: R747.1 U518.6
UNNAMED_38_ADP2114_I358_SS1: C745.2(N2) U518.30
UNNAMED_38_ADP2114_I358_SS2: C746.2(N2) U518.11
UNNAMED_38_ADP2114_I358_SW1: L521.1 U518.23 U518.24
UNNAMED_38_ADP2114_I358_SW3: L520.1 U518.17 U518.18
UNNAMED_38_ADP2114_I447_FREQ: R74.2(N2) U6.3
UNNAMED_38_ADP2114_I447_OPCFG: R75.2(N2) U6.6
UNNAMED_38_ADP2114_I447_SS1: C193.2(N2) U6.30
UNNAMED_38_ADP2114_I447_SS2: C194.2(N2) U6.11
UNNAMED_38_ADP2114_I447_SW1: L9.1 U6.23 U6.24
UNNAMED_38_ADP2114_I447_SW3: L8.1 U6.17 U6.18
UNNAMED_38_ADP2114_I447_V1SET: R91.1 R92.1 U6.31
UNNAMED_38_ADP2114_I447_V2SET: R149.1 R203.1 U6.10
UNNAMED_38_CAP_I366_N2: C757.2(N2) R760.2(N2)
UNNAMED_38_CAP_I379_N1: C761.1 C762.1 E768.1 L521.2(N2) R765.2(N2)
UNNAMED_38_CAP_I387_N2: C753.2(N2) R752.2(N2)
UNNAMED_38_CAP_I457_N1: C215.1 E21.1 L8.2(N2) R205.1
UNNAMED_38_CAP_I463_N1: C207.1 R90.2(N2)
UNNAMED_38_CAP_I465_N2: C203.2(N2) R204.1
UNNAMED_39_ICUSB3320C_I29_RBIAS: R800.1 U524.24
UNNAMED_39_ICUSB3320C_I29_REFCL: R797.1 U524.26
UNNAMED_39_RES_I67_N2: R797.2(N2) Y523.3
UNNAMED_40_ICXC7Z010_I16_PSCLK5: R581.2(N2) U511.C7
UNNAMED_40_ICXC7Z010_I16_PSMIO7: R584.2(N2) U511.D9
UNNAMED_40_ICXC7Z010_I16_PSMIO8: R592.1 U511.B6
UNNAMED_40_RES_I48_N1: R581.1 Y578.3
UNNAMED_41_CAP_I89_N1: C644.1 R642.2(N2) U509.5(VTTSNS)
UNNAMED_41_ICMT41K256M16_I99_ZQ: R661.1 U646.L8(ZQ)
UNNAMED_41_ICTPS51206_I44_S3: R640.2(N2) U509.7
UNNAMED_41_ICTPS51206_I44_S5: R638.2(N2) U509.9
UNNAMED_41_ICTPS51206_I44_VLDOI: R653.2(N2) U509.2
UNNAMED_41_ICXC7Z010_I26_PSDD_1: R634.1 U511.H3
UNNAMED_41_ICXC7Z010_I26_PSDDRV: R635.1 U511.J3
UNNAMED_42_CAP_I17_N1: C684.1 C688.1 E682.2(N2) U511.F7
UNNAMED_42_CAP_I17_N2: C684.2(N2) C688.2(N2) E687.2(N2) U511.F8 U511.G8 U511.H7 U511.J7
UNNAMED_42_DIOLED_I60_N: DS11.C R691.1
UNNAMED_42_DIOLED_I74_N: DS12.C R215.1
UNNAMED_42_ICXC7Z010_I13_CFGBVS: R216.2(N2) U511.F6
UNNAMED_42_ICXC7Z010_I13_DONE0: Q512.1 U511.M7
UNNAMED_42_ICXC7Z010_I13_INITB0: R689.1 U511.D5
UNNAMED_42_ICXC7Z010_I13_PROGRA: R685.1 U511.K6
UNNAMED_42_ICXC7Z010_I13_VCCBAT: R681.2(N2) U511.E6
UNNAMED_42_ICXC7Z010_I13_VP0: R148.2(N2) R213.1 U511.G7
UNNAMED_42_RES_I61_N2: Q1.3 R691.2(N2)
UNNAMED_42_RES_I73_N2: Q2.3 R215.2(N2)
UNNAMED_42_TRANNMOSFETV8_I36_D: Q1.2(S) Q512.3
UNNAMED_43_ADP5589V2_I25_RSTN: R87.2(N2) U15.17
UNNAMED_45_ADP198_I317_VOUT: C280.1 C281.1 F1.1 R212.1 U16.A2(VOUT)
UNNAMED_45_CAP_I416_N1: C312.1 C313.1 L10.1 U21.9 U21.10 U21.15 U21.16
UNNAMED_45_CHOKE4P_I331_N2: D739.C L1.2 P516.3
UNNAMED_45_CHOKE4P_I331_N3: D741.C L1.3 P516.2
UNNAMED_45_CN5P3SHLD_I255_N6: P516.SH1 P516.SH2 P516.SH3(N8) R744.1
UNNAMED_45_CN5P3SHLD_I256_N6: P519.SH1 P519.SH2 P519.SH3(N8) R749.1
UNNAMED_45_LINLTC4415_I406_CL_1: R192.1 U21.5
UNNAMED_45_LINLTC4415_I406_CLIM: R191.2(N2) U21.4
USB_ID: P516.4 U524.23
USB_OTG_CPEN: U16.B1 U524.17
USB_OTG_N: L1.4(N4) U524.19
USB_OTG_P: L1.1 U524.18
USB_VBUS_OTG: C324.1 R156.1 R212.2(N2) U524.22
USR_BTN: R145.2(N2) S1.1 U511.B9
USR_LED: Q2.1 R214.1 U511.D10
VTT_0P75: C615.1 C662.1 R601.2(N2) R602.2(N2) R603.2(N2) R604.2(N2) R605.2(N2) R606.2(N2) R608.2(N2) R609.2(N2) R610.2(N2) R611.2(N2) R612.2(N2) R613.2(N2) R619.2(N2) R620.2(N2) R621.2(N2) R622.2(N2) R623.2(N2) R624.2(N2) R627.2(N2) R628.2(N2) R629.2(N2) R630.2(N2) R631.2(N2) R632.2(N2) R642.1 U509.3
VTTVREF: C650.2(N2) C654.1 C657.1 C660.1 C692.2(N2) U509.6 U511.F4 U646.H1 U646.M8
VTUNE: C239.1 R86.2(N2) U14.7

Pads without a net: A1 12; A2 12; A4 12; A7 6; A9 6; P519 2 3 4; S1 2 5; U6 5; U8 2 5 7 8 13; U9 2 5 7 8 13; U13 5; U14 20; U15 24; U21 12 13; U508 A2 A3 A5 B1 B5 C1 C3 C5 D1 D5 E1 E2 E3 E4 E5; U511 B5 B10 B12 C13 D6 D8 D13 F15; U518 5; U524 12 15 16 25; U646 J1 J9 L1 L9 M7; Y1 1; Y523 1; Y578 1

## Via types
v1: diameter 0.508, hole 0.254, TOP to BOTTOM, 1665 vias
v2: diameter 0.406, hole 0.203, TOP to BOTTOM, 498 vias

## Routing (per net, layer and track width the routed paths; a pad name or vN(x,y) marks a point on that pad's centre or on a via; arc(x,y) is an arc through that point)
1.35V: length 6.7
  BOTTOM w0.305: R763.1 v1(89.69,40.88)
  BOTTOM w0.762: 91.76,43.95 C758.1 92.81,43.05 ; 90.4,43.05 C754.1 91.45,43.95 ; 91.98,42.37 E767.1 91.16,41.48
  vias: v1(89.69,42.15) v1(89.69,41.51) v1(90.33,42.15) v1(90.33,41.51) v1(90.33,40.88) v1(90.96,42.15) v1(90.96,41.51) v1(90.96,40.88)
1V0_D: length 7.1
  TOP w1.016: 87.86,45.72 C241.1 86.8,46.62
  BOTTOM w0.203: R207.1 85.7,46.75 E26.1
  BOTTOM w1.016: 86.46,46.68 E26.1 85.63,45.79 ; 87.98,45.84 C208.1 86.93,46.75
  vias: v1(86.4,45.54) v1(86.33,44.9) v1(86.97,45.54) v1(86.97,44.9) v1(87.6,45.54) v1(87.6,44.9) v1(88.24,45.54) v1(88.24,44.9) v1(88.87,45.54) v1(88.87,44.9)
1V8_A_1: length 45.9
  TOP w0.254: v1(57,47.57) 57.01,47.56 U2.8 ; v1(57,48.21) 57.14,48.06 U2.7 ; U2.9 57.12,47.06 v1(57,46.94)
  BOTTOM w0.305: 57.29,47.57 C38.1 ; C38.1 57.69,48.03 ; C38.1 57.69,47.11 ; 49.12,49.6 49.12,47.13 48.87,46.87 48.11,46.87 46.39,45.16 43.66,45.16 43.09,44.59 43.09,43.57 42.77,43.25 41.44,43.25 41.12,42.94 R56.1 ; 49.12,49.6 46.52,49.6 45.15,50.98 45.15,52.06 42.85,54.35 R30.1 ; 49.12,49.6 54.33,49.6 54.65,49.92 55.73,49.92 56.42,49.22 56.42,48.59 56.81,48.21 v1(57,48.21) ; 55.92,46.1 C57.1 ; C57.1 55.92,47.01 ; C57.1 56.32,46.56 ; C48.1 57.69,47.01 ; C48.1 57.69,46.1 ; C48.1 57.29,46.56 ; 57.29,48.59 C43.1 57.69,48.13 ; C53.1 55.92,48.03 ; C53.1 55.92,47.11 ; C53.1 56.32,47.57 ; C28.1 56.41,43.89 ; C28.1 55.91,43.35 ; C28.1 55.91,44.42 ; C33.1 55.91,45.95 ; C33.1 56.41,45.41 ; C33.1 55.91,44.88 ; 56.32,48.59 C61.1 55.92,48.13 ; 55.98,43.08 E2.2 56.59,42.53
1V8_A_2: length 14.5
  TOP w0.254: U2.55 67.09,52.77 C45.1 ; U2.53 68.18,50.56 68.32,50.71 68.32,50.96 v1(68.87,51.51)
  TOP w0.305: C39.1 v1(68.87,51.51) ; C45.1 67.98,53.1 68.55,53.67 v1(69.06,53.67)
  BOTTOM w0.305: 68.64,51.51 C34.1 68.24,51.97 ; C25.1 69.59,54.5 ; C25.1 69.06,54 ; C25.1 68.53,54.5 ; 69.1,51.64 C50.1 69.51,52.09 ; C58.1 68.64,53.54 ; C58.1 68.24,53.08 ; C58.1 68.24,54 ; 69.68,52.97 E3.2 ; E3.2 70.23,53.58 ; E3.2 70.23,52.36 ; 70.2,54 C29.1 69.67,54.5 ; C54.1 68.64,52.52 ; C54.1 68.24,52.98 ; C54.1 68.24,52.07
  vias: v1(69.06,52.78)
1V8_D: length 72.3
  TOP w0.254: C44.1 C41.1 ; U2.52 68.73,50.06
  TOP w0.305: v1(72.45,12.86) C579.1 72.87,14.4 Y578.4 ; v2(83.72,27.62) 83.72,27.62 83.72,28.19 ; U524.32 v1(64.87,29.75) ; v1(62.33,28.65) 62.33,28.65 U524.28 ; v1(72.64,21.56) 73.2,21 R791.1 ; U511.L6 v2(85.42,27.06) ; U511.B13 v2(76.37,25.92) ; U524.8 65.03,34.53 v1(65.06,34.55) ; U511.H9 v2(82.59,26.49) ; v1(59.66,28.59) C795.2 ; U511.J8 v2(84.29,27.06) ; 78.07,28.19 v2(77.5,28.19) ; 79.2,24.79 v2(78.63,24.79) ; U524.30 63.33,28.66 v1(63.35,28.65) ; 69.03,49.86 C41.1 ; U508.B4 v2(68.2,5.3) ; v1(63.22,35.51) 63.33,35.39 U524.11 ; U511.A6 v2(79.97,21.04) ; 69.03,50.68 C44.1 ; U511.D7 v2(81.46,23.1) ; 84.85,25.92 v2(85.42,25.92) ; v1(61.83,35.57) U524.14
  TOP w0.356: Y523.4 58.9,27.5 C795.2
  TOP w0.406: R592.2 77.4,13.48 v1(77.4,13.39) ; C805.1 63.79,28.14 63.35,28.58 v1(63.35,28.65) ; v1(102.79,24.33) R145.1 ; v1(94.14,34.49) R148.1 ; v1(62.33,28.65) C803.1
  L6_SIG w0.406: v1(59.66,28.59) 62.27,28.59 v1(62.33,28.65)
  BOTTOM w0.305: R584.1 75.79,19.97 v1(75.79,19.84) ; C589.1 68.58,5.69 v2(68.2,5.3) ; C20.1 55.85,40.8 ; C20.1 55.85,39.74 ; C20.1 56.34,40.27 ; C598.1 80.2,20.81 v2(79.97,21.04) 79.75,21.27 C599.1 79.15,21.61 78.8,21.61 R681.1 ; R591.2 v1(66.6,9.14) ; C668.1 83.36,27.99 v2(83.72,27.62) ; C792.1 77.33,28.01 v2(77.5,28.19) ; 72.19,51.38 C21.1 ; C21.1 72.69,51.92 ; C21.1 72.69,50.85 ; 71.74,52.97 E3.1 71.19,52.36 ; C31.1 68.23,50.49 C36.1 68.3,50.56 v1(68.87,50.56) 69.31,50.56 C49.1 ; 56.59,41.56 E2.1 55.98,41.02 ; C679.1 74.62,28.23 v2(74.62,28.78) 74.62,29.31 C683.1 ; C793.1 78.18,24.34 v2(78.63,24.79) 78.05,25.38 R798.1 ; R585.1 v1(69.78,13.11)
  BOTTOM w0.406: C790.1 74.27,24.4 v2(74.27,24.58) 74.27,25.79 C664.1 74.52,25.85 75.03,25.35 v2(75.03,24.58) 75.03,24.3 C790.1 ; C790.1 74.78,23.97 v2(75.16,23.58) 75.55,23.2 C789.1 ; v1(63.35,28.65) 63.35,28.72 C807.1 62.33,28.72 v1(62.33,28.65) ; E682.1 v1(82.62,9.06) ; 72.92,6.3 v1(73.63,6.3) ; v1(76.79,12.63) C675.1 76.43,13.29 76.43,14.01 E677.1 ; C597.1 72.72,29.32 v2(72.72,28.78) 72.72,28.24 C666.1
  BOTTOM w0.508: v1(100.95,27.58) v1(100.5,28.03) 100.03,28.5 100.03,28.92 ; v1(70.58,26.91) 69.53,26.91 C676.1 69.7,27.76 v1(70.58,27.76) ; C789.1 75.64,23.12 v2(76.01,22.74) 76.4,22.36 C596.1
  BOTTOM w0.762: 97.51,40.33 E768.2 98.33,41.22 ; 73.62,19.95 74.51,19.06 ; 73.62,19.95 74.36,20.7 ; 73.62,19.95 72.73,20.84 ; 97.45,44.08 C774.1 96.75,43.44 ; 72.08,21.48 C788.1 71.94,23.12
  vias: v1(68.62,35.82) v1(69.25,35.82) v1(69.89,35.82) v1(72.11,21.03) v1(73.12,22.04) v1(74.89,18.94) v1(75.34,19.39) v1(96.75,42.11) v1(96.75,41.6) v1(96.75,41.09) v1(96.75,40.59) v1(96.75,40.08) v1(97.25,42.11) v1(97.25,41.6) v1(97.25,41.09) v1(97.25,40.59) v1(97.25,40.08)
1V35: length 32.2
  TOP w0.203: U509.1 v1(100.48,29.83)
  TOP w0.305: U646.G7 v2(93.93,12.2) ; U646.E9 v2(91.67,13.33) ; U646.F1 v2(96.76,8.24) ; U646.D9 v2(91.1,12.76) ; U511.B3 v2(82.59,19.7) ; v2(86.55,21.4) 86.55,21.4 U511.F1 ; U646.K8 v2(95.06,15.59) ; U646.R1 102.41,13.89 v2(102.41,13.89) ; 89.38,28.19 v2(89.73,28.54) ; U646.A8 v2(89.4,9.93) ; U646.R9 97.32,17.86 v2(97.32,17.86) ; U511.J2 v2(87.68,23.66) ; U646.K2 v2(99.02,11.63) ; v2(80.33,16.86) 80.21,16.86 C626.1 ; U646.N1 v2(101.29,12.76) ; U646.H9 v2(93.36,15.03) ; 96.19,17.29 96.19,16.72 v2(96.19,16.72) ; 93.93,7.11 93.93,6.84 v2(93.93,6.54) ; U646.A1 v2(93.93,5.41) ; U646.H2 v2(97.32,9.94) ; U511.M3 v2(88.81,25.92) ; U646.D2 v2(95.06,7.67) ; U511.E4 v2(83.72,21.96) ; U646.C9 v2(89.97,11.63) ; 95.06,7.11 v2(95.06,6.54)
  TOP w0.406: v2(89.95,20.83) 89.55,20.43 C616.1 ; C614.1 91.02,31.64 v1(90.53,31.15) ; v2(91.22,22.1) 90.83,21.7 C617.1
  BOTTOM w0.305: v2(93.93,12.2) 93.93,12.31 C649.1 ; v2(99.02,11.63) 98.15,11.63 C645.1 ; C643.1 94.4,4.94 v2(93.93,5.41) ; v2(89.4,9.93) 89.29,9.93 C658.1 ; C641.1 89.5,11.16 v2(89.97,11.63) ; C647.1 93.36,14.91 v2(93.36,15.03) ; C639.1 97.77,18.31 v2(97.32,17.86) ; C651.1 95.31,6.54 v2(95.06,6.54) ; v2(102.41,13.89) 102.53,13.89 C655.1 ; C652.1 96.76,8.11 v2(96.76,8.24) ; 95.6,40.52 UNK1V35.1 94.84,39.76 ; C633.1 89.95,29.35
  BOTTOM w0.406: R635.2 87.28,23.26 v2(87.68,23.66) 88.06,24.04 C618.1 ; 89.95,29.35 89.95,28.76 v2(89.73,28.54) ; v2(86.55,21.4) 86.55,21.4 86.88,21.07 C607.1
  BOTTOM w0.762: 94.4,44.08 C769.1 95.1,43.44 ; 93.89,40.59 E767.2 ; E767.2 94.72,41.48 ; E767.2 93.89,42.37
  vias: v1(94.97,43.13) v1(94.97,42.49) v1(94.97,41.86) v1(94.97,41.22) v1(94.97,40.59) v1(95.6,43.13) v1(95.6,42.49) v1(95.6,41.86) v1(95.6,41.22) v1(95.6,40.59) v2(88.7,18.43) v2(89.12,18)
3V3_A: length 31.3
  TOP w0.305: 18.26,6.89 C282.1 17.8,6.49 ; v1(52.33,26.49) A11.8 ; 16.04,7.02 A14.6 16.54,6.57 ; 16.79,6.49 C202.1 ; C202.1 17.24,6.89 ; C202.1 17.7,6.49
  TOP w0.406: v1(28.42,18.74) 28.42,18.87
  TOP w0.508: E8.2 29.21,18.34 ; E8.2 29.21,17.12 ; E8.2 28.66,17.73
  BOTTOM w0.305: 56.04,55.17 C22.1 ; C22.1 56.53,55.7 ; C22.1 56.04,56.23 ; 41.94,36.93 C205.1 42.44,36.4 ; 39.26,20.9 C284.1 38.76,21.44 ; 57.76,56.7 E12.1 57.15,57.25 ; 57.5,55.36 R76.1 57,54.86 ; C306.1 C298.1 52.35,26.43 52.33,26.45 v1(52.33,26.49) ; C47.1 18.13,7.1 ; C47.1 C14.1 ; C47.1 18.67,6.61 ; 38.52,21.59 C286.1 38.92,22.04 ; C14.1 17.12,7.1 ; C14.1 16.58,6.61 ; 56.53,57.22 C204.1 56.04,56.69 ; 31.65,22.32 C285.1 32.15,21.79 ; 31.81,23.31 C287.1 31.41,22.86 ; 39.47,22.3 40.11,22.3 U18.4
  BOTTOM w0.406: 40.3,21.88 U18.4 41.05,22.49 ; 35.34,22.77 U19.3 34.59,23.38 ; U19.4 33.69,23.38 ; U19.4 32.19,23.38 ; U19.4 32.94,22.77 ; 41.95,22.49 U18.3 42.7,21.88
  BOTTOM w0.508: UNK3V3_A.1 29.06,15.44 v1(29.06,16.2) v1(28.42,16.2) ; v1(36.11,28.33) C206.1 35.86,27.25 E10.1
  vias: v1(17.24,7.31) v1(18.26,7.31) v1(28.42,18.11) v1(28.42,17.47) v1(28.42,16.84) v1(29.06,18.74) v1(29.06,16.84) v1(31.6,22.55) v1(32.23,22.55) v1(41.63,22.17) v1(41.63,21.54) v1(42.77,37.03) v1(42.77,36.27) v1(56.11,54.94) v1(56.74,55.57) v1(56.74,54.94)
3V3_A_1: length 15
  TOP w0.254: v1(57,51.38) 57.32,51.06 U2.1 ; U2.58 v1(65.59,52.52) ; U2.67 v1(61.09,52.52) ; v1(64.11,52.5) 64.09,52.48 U2.61
  TOP w0.305: C55.1 63.6,53.01 v1(64.11,52.5)
  BOTTOM w0.305: C59.1 C40.1 ; C59.1 62.28,51.83 ; C59.1 61.82,52.23 ; C40.1 61.06,52.23 ; C40.1 60.6,51.83 ; C46.1 v1(64.11,52.5) ; C46.1 63.65,51.83 ; C46.1 64.57,51.83 ; 65.17,51.83 C51.1 65.63,52.23 ; 57.41,51.25 C35.1 57.82,51.71 ; 57,54 R76.2 ; R76.2 58.01,54 ; R76.2 57.5,53.5 ; 61.06,54.38 C26.1 ; C26.1 61.59,54.88 ; C26.1 60.53,54.88 ; 62.46,54.38 C30.1 ; C30.1 62.99,54.88 ; C30.1 61.92,54.88
3V3_AWG_A: length 8.1
  TOP w0.305: 34.07,28.66 C246.1 C253.1 C250.1 34.2,31.32 35.41,31.32 35.53,31.44 A10.8 ; 34.07,28.66 34.07,28.65 34.07,28.39 ; 34.07,28.66 34.07,28.64 C244.1 34.07,28.39 ; 34.07,28.39 34.07,27.75 C242.1
  TOP w0.508: C242.1 33.69,27.38 v1(32.99,27.38)
  BOTTOM w0.508: v1(32.99,27.38) 33.91,27.38 E10.2
3V3_CLK_A: length 18.3
  TOP w0.254: v1(61.57,59.13) v1(61.06,59.13)
  TOP w0.305: v1(68.3,57.48) 68.49,57.67 C232.1 C234.1 68.37,58.76 U14.2 ; U14.6 67.77,60.76 67.92,60.91 C229.1 C233.1 68.49,62.24 v1(68.43,62.3) ; v1(64.87,56.33) 65.13,56.59 U14.21 ; L15.2 v1(71.35,58.29) ; v1(62.58,65.99) 62.39,65.8 C225.1 ; C225.1 60.56,65.8 Y1.4 ; C225.1 C224.1 ; L16.2 v1(71.35,61.74)
  BOTTOM w0.305: C228.1 61.59,58.17 ; C228.1 61.06,58.67 ; C228.1 60.53,58.17 ; C226.1 59.54,59.07 ; C226.1 60.23,58.43 ; C226.1 58.84,58.43 ; v1(64.87,56.33) 65.06,56.53 C235.1 C231.1 ; 58.37,58.21 E12.2 57.76,58.76
3V3_D: length 121.1
  TOP w0.203: 53.58,34.25 U15.18
  TOP w0.254: 53.58,34.25 53.31,33.98 v1(53.31,33.28) ; v1(58.9,41.22) 59.09,41.41 U2.20 ; v2(65.5,41.22) 65.59,41.3 U2.33 ; v1(69,49.22) 68.62,49.22 68.28,49.56 U2.51 ; C96.1 v1(26.58,20.52) ; R142.1 v1(22.69,17.55)
  TOP w0.305: v2(84.29,28.19) 84.29,28.19 U511.K8 ; v2(92.68,33.67) 94.89,33.67 R130.1 ; U20.9 26.57,21.15 C96.1 ; U524.21 59.4,31.95 59.28,32.08 v1(59.28,32.46) 59.29,32.45 U524.20 ; U511.H4 v2(85.42,23.66) ; U511.M13 v2(82.59,32.15) ; v1(53.31,33.28) C240.1 R87.1 ; 84.85,30.45 v2(84.85,31.01) ; U511.H15 v2(78.77,30.87) ; U511.F11 v2(79.76,27.06) ; U511.P7 v2(87.69,29.32) ; U511.R14 v2(84.12,34.24) ; U511.G4 v2(84.85,23.1) ; U511.J12 v2(81.46,29.88) ; U511.J4 v2(86.55,24.79)
  TOP w0.406: R689.2 v1(79.75,14.64) ; v1(59.28,32.46) 58.59,32.46 C801.1
  TOP w0.508: v1(65.38,6.17) P510.10
  TOP w1.016: 76.86,37.92 C696.1
  L5_SIG w0.508: v1(69,49.22) 69,49.6 69.89,50.49 69.89,53.99 74.46,58.56 74.46,64.53 75.92,65.99 78.46,65.99 80.3,64.15 82.71,64.15 84.49,62.37 98.23,62.37 v1(98.51,62.64)
  BOTTOM w0.203: R144.1 34.64,28.57 34.64,28.81 v2(35.34,29.51) ; C7.1 v2(65.5,41.22) 65.5,41.74 C32.1
  BOTTOM w0.254: v1(26.69,17.8) R140.1 26.58,18.73 v1(26.58,20.52) ; C710.1 79.77,27.06 v2(79.76,27.06)
  BOTTOM w0.305: R217.1 76.06,31.56 R211.1 76.22,31.62 76.43,31.82 77.64,31.82 C698.1 ; C37.1 v1(69,49.22) C60.1 ; U11.3 35.58,30.28 C299.1 v2(35.34,29.51) ; R210.1 78.43,30.37 C712.1 78.43,30.53 v2(78.77,30.87) ; R14.1 58.84,39.94 C42.1 58.84,41.16 v1(58.9,41.22) 58.9,41.86 C27.1 ; C707.1 83.56,34.24 v2(84.12,34.24) 84.69,34.24 C705.1 ; R685.2 90.19,32.71 v2(89.8,33.09) 89.8,33.71 C701.1 ; C711.1 82.72,32.15 v2(82.59,32.15) ; C713.1 87.95,29.32 v2(87.69,29.32)
  BOTTOM w0.406: R216.1 80.42,14.64 v1(79.75,14.64) ; v1(58.7,9.9) R209.1 59.28,10.49 59.54,10.23 v1(59.54,9.85) ; C703.1 82.47,32.15 v2(82.59,32.15) ; C709.1 85.24,30.62 v2(84.85,31.01) ; C700.1 79.58,33.69 v2(80.04,34.15) 80.49,34.6 C706.1 ; C698.1 77.88,31.99 v2(78.34,32.44) 78.79,32.9 78.79,32.98 ; R196.1 R195.1 v1(98.51,62.64) ; C708.1 87.67,32.87 v2(88.1,32.45) 88.53,32.02 C704.1
  BOTTOM w0.508: C699.1 92.69,30.87 v2(92.69,31.29) 92.69,32.06 92.29,32.46 C678.1 92.68,32.9 v2(92.68,33.67) ; v1(27.4,15.69) 27.4,14.81 28.42,13.79 28.42,12.27 31.09,9.6 R155.1 ; v1(38.15,28.33) R119.1
  BOTTOM w0.635: 79.03,46.56 E21.2 78.2,45.67
  BOTTOM w0.762: 79.41,47 C278.1 80.11,46.36
  BOTTOM w1.016: 76.86,37.67 C697.1 77.76,38.72
  vias: v1(75.92,39.06) v1(75.92,38.43) v1(76.55,39.06) v1(76.55,38.43) v1(77.95,44.14) v1(77.95,43.51) v1(78.59,44.14) v1(78.59,43.51) v1(79.22,44.14) v1(79.22,43.51) v1(79.86,44.14) v1(79.86,43.51)
3V3_D_LA: length 103.1
  TOP w0.305: D11.2 12.54,16.85 13.31,16.08 14.2,16.08 14.97,16.85 D10.2 ; D8.2 14.97,21.16 14.2,20.39 13.31,20.39 12.54,21.16 D13.2 ; D17.2 12.54,29.8 13.31,29.03 14.2,29.03 14.97,29.8 D4.2 ; D3.2 14.97,34.12 14.32,33.47 13.18,33.47 12.54,34.12 D19.2 ; D18.2 12.54,31.96 13.43,31.06 14.07,31.06 14.97,31.96 D2.2 ; D9.2 14.97,19 14.2,18.23 13.31,18.23 12.54,19 D12.2 ; D14.2 12.54,23.32 13.31,22.55 14.2,22.55 14.97,23.32 D7.2 ; D5.2 14.97,27.64 14.2,26.87 13.31,26.87 12.54,27.64 D16.2 ; D6.2 14.97,25.48 14.2,24.71 13.31,24.71 12.54,25.48 D15.2
  TOP w0.508: D15.2 v1(11.66,25.48) ; D14.2 v1(11.66,23.32) ; D19.2 11.79,34.12 v1(11.53,33.86) ; D16.2 v1(11.66,27.64) ; D11.2 v1(11.66,16.85) ; D12.2 v1(11.66,19) ; D13.2 v1(11.66,21.16) ; D18.2 v1(11.66,31.96) ; D17.2 v1(11.66,29.8)
  L6_SIG w0.635: 7.59,15.44 7.59,8.71 8.86,7.44 10.77,7.44 12.14,8.81 16.08,8.81 16.99,9.73 30.33,9.73 31.47,8.58 40.17,8.58 42.01,10.42 47.41,10.42 50.77,13.79 56.11,13.79 57.84,12.06 v1(57.84,9.85) v1(57,9.85)
  BOTTOM w0.406: v1(57,9.85) 57,10.23 57.25,10.49 R209.2 v1(57.84,9.85)
3V3_SC_A: length 30.9
  TOP w0.305: 41.21,55.45 C119.1 40.8,54.99 ; C115.1 41.21,54.43 ; C115.1 40.8,53.97 ; C115.1 40.8,54.89 ; 43.71,39 C160.1 ; C160.1 44.17,39.41 ; C160.1 44.63,39 ; 45.05,52.44 U3.10 ; 44.55,52.44 U3.9 ; 42.05,43 U4.4 ; C158.1 43.15,39.41 ; C158.1 42.7,39 ; C158.1 43.61,39 ; 45.05,40.5 U4.10 ; 42.7,50.94 C111.1 ; C111.1 C109.1 ; C111.1 43.15,51.34 ; 44.73,39 C170.1 45.18,39.41 ; 40.54,39.8 C156.1 41.04,40.33 ; 42.05,43.5 U4.3 ; C109.1 C117.1 45.18,51.34 ; C109.1 44.17,51.34 ; C154.1 41.88,39.89 ; C154.1 42.58,39.25 ; C154.1 41.18,39.25 ; 40.92,51.74 C107.1 ; C107.1 40.92,52.8 ; C107.1 41.42,52.27 ; C113.1 41.21,53.41 ; C113.1 40.8,53.87 ; C113.1 40.8,52.96 ; 41.21,43.51 C168.1 40.8,43.05 ; C166.1 41.21,41.48 ; C166.1 40.8,41.02 ; C166.1 40.8,41.93 ; 42.05,54.94 U3.4 ; 40.8,42.03 C164.1 ; C164.1 41.21,42.49 ; C164.1 40.8,42.95 ; R47.1 37.82,38.94 38.33,39.44 40.52,39.44 ; 42.05,55.44 U3.3 ; 44.55,40.5 U4.9
  TOP w0.635: 42.2,50.68 C105.1 41.5,51.32
  BOTTOM w0.305: 41.27,39.29 E9.2 41.88,39.84
  vias: v1(41.25,40.33) v1(41.76,40.33) v1(41.88,52.78) v1(41.88,52.14) v1(41.88,51.51) v1(42.26,40.33)
4V0_A: length 24.4
  TOP w0.305: C331.1 31.66,59.64 C330.1 v1(32.4,59.76) ; C331.1 C332.1 32.23,57.99 32.36,58.11 A3.8 33.25,59.46 ; C331.1 32.07,58.87 ; C142.1 32.69,48.27 ; C142.1 31.77,48.27 ; C142.1 32.23,47.86 ; 32.05,62.2 C311.1 31.55,61.67 ; 31.09,47.78 C144.1 ; C144.1 31.62,48.28 ; C144.1 v1(30.4,48.28) ; 33.25,47.86 C141.1 32.79,48.27 ; 31.31,63.26 U17.5 32.33,62.75
  TOP w0.508: A5.8 33.25,47.52
  L6_SIG w0.406: v1(31.34,61.41) v1(31.34,62.05) 31.34,62.56 32.1,63.32 34.64,63.32 36.55,61.41 v1(37.44,61.41)
  BOTTOM w0.203: R164.1 31.34,62.89 v1(31.34,62.05)
  BOTTOM w0.508: 32.13,62.02 E1.2 31.58,61.41
5V0_A: length 19.5
  TOP w0.203: 37.96,14.58 U7.1 37.55,15.3 ; U7.2 37.05,15.3
  TOP w0.305: C180.1 39.34,14.77 ; 34.67,62.75 U17.1 35.69,63.26 ; 54.09,16.47 U10.13 53.68,17.12 ; 52.69,17.87 U10.12 53.34,17.46 ; U7.1 U7.2 ; 35.76,63.26 C310.1 ; C310.1 36.29,62.77 ; C310.1 36.83,63.26
  TOP w0.508: 45.82,3.59 R68.2 45.31,4.09
  TOP w0.635: 46.26,3.06 C18.1 46.96,2.42 ; 83.92,61.54 E4.2 84.81,62.37 ; 83.98,61.2 C5.1 84.89,60.14 ; 50.39,17.6 C2.2 51.24,16.8
  TOP w1.016: 39.04,17.35 C177.1 38.14,16.29
  BOTTOM w1.016: 39.17,17.47 C19.1 38.26,16.42
  vias: v1(37.56,63.19) v1(37.56,62.56) v1(39.34,17.6) v1(39.34,16.96) v1(39.34,16.33) v1(39.98,17.6) v1(39.98,16.96) v1(39.98,16.33) v1(45.18,3.25) v1(45.18,2.61) v1(45.18,1.98) v1(45.82,3.25) v1(45.82,2.61) v1(45.82,1.98) v1(46.45,1.98) v1(47.09,1.98) v1(51.79,17.73) v1(51.79,17.09) v1(51.79,16.46) v1(52.42,17.73) v1(52.42,17.09) v1(85.19,61.67) v1(85.19,61.03) v1(85.19,60.4) v1(85.19,59.76) v1(85.82,61.67) v1(85.82,61.03) v1(85.82,60.4) v1(85.82,59.76)
6V0_A: length 22.9
  TOP w0.508: 21.27,11.43 C214.1 20.74,11.93 ; 21.26,13.09 E18.1 20.71,12.48
  TOP w0.635: C99.1 43.91,15.22 ; C99.1 44.88,14.66 ; C99.1 43.91,14.1 ; C99.1 42.95,14.66 ; 45.95,14.49 C176.1 45.25,13.85
  TOP w0.762: 41.25,14.93 L7.2 42.39,14.17
  BOTTOM w0.203: 46.45,14.04 47.34,14.04 47.6,13.79 R73.2
  BOTTOM w0.305: 28.43,23.95 E17.1 27.89,23.34 ; 46.45,14.68 UNK6V0_A.1 45.69,15.44 ; 28.65,23.89 C213.1 29.18,23.4
  BOTTOM w0.508: E14.1 45.25,25.06 C212.1 45.25,22.84 45.46,22.63 45.46,20.74 v1(45.18,20.46) v1(44.42,20.46)
  BOTTOM w1.016: C101.1 44.97,14.36 ; C101.1 43.91,15.26 ; C101.1 42.86,14.36
  vias: v1(21.63,12.08) v1(21.63,11.44) v1(28.04,23.06) v1(28.67,23.06) v1(29.31,23.06) v1(42.64,15.57) v1(42.64,14.93) v1(43.28,15.57) v1(44.04,15.57) v1(44.8,15.57) v1(45.44,15.57) v1(45.44,14.93)
6V0_AWG_A: length 20
  TOP w0.305: v1(25.37,32.84) 25.64,33.11 A9.8 ; v1(26.01,23.95) 28.85,23.95 R201.1 ; v1(25.5,27) 25.77,27.26 A7.8
  BOTTOM w0.102: v1(28.8,32.46) R202.1 ; v1(26.01,22.93) 25.94,23
  BOTTOM w0.305: 25.94,23 C300.1 C301.1 23.4,23 22.99,22.59 A13.8 ; v1(28.93,26.49) 28.22,26.49 C258.1 C262.1 26.64,26.55 C264.1 C268.1 v1(25.5,27) ; v1(25.37,32.84) C276.1 C274.1 26.51,32.52 C272.1 C270.1 28.1,32.46 v1(28.8,32.46) ; 26.92,23.34 E17.2 26.38,23.95
6V0_SC_A: length 30.9
  TOP w0.305: A8.8 45.25,34.66 C295.1 C294.1 45.25,32.14 v1(45.44,31.95) ; v1(26.95,45.22) 27.21,45.48 A1.13 ; A4.13 27.21,57.17 v1(27.2,57.16) ; v1(46.58,28.39) 46.14,28.39 C288.1 C290.1 45.15,28.24 A6.8 ; v1(25.73,48.21) 26.32,48.21 C87.1 26.51,48.4 C86.1 C84.1 28.36,48.21 v1(28.8,48.21)
  BOTTOM w0.305: A2.13 28.86,48.15 v1(28.8,48.21) ; 38.76,36.84 C150.1 ; C150.1 39.22,37.25 ; C150.1 39.67,36.84 ; 39.63,47.95 C335.1 ; C335.1 40.04,48.41 ; C335.1 40.04,47.49 ; 39.77,36.84 C149.1 40.23,37.25 ; v1(27.2,57.16) C78.1 C79.1 24.86,57.16 C80.1 24.61,57.41 24.61,57.6 v1(24.23,57.99) ; U9.11 38.51,37.34 ; v1(26.95,45.22) 26.83,45.1 C135.1 C136.1 24.6,45.1 C137.1 v1(23.72,45.22) ; 39.53,49.22 C334.1 40.04,48.76 ; 39.7,37.86 C152.1 40.23,37.37
  BOTTOM w0.508: 33.64,61.41 E1.1 33.09,60.8 ; E14.2 44.55,27.1 v1(44.55,28.39) v1(44.55,29.16)
  vias: v1(32.99,60.53) v1(33.63,60.53) v1(38.83,37.48) v1(39.15,46.94) v1(39.47,37.48)
6V0_USR_A: length 7.4
  TOP w0.305: 16.79,12.2 C318.1 ; C318.1 17.7,12.2 ; C318.1 17.24,12.61 ; 17.8,12.2 C322.1 ; C322.1 18.72,12.2 ; C322.1 18.26,12.61 ; 16.04,12.74 A12.6 16.54,12.28
  TOP w0.508: 19.2,13.09 E18.2 19.75,12.48
  BOTTOM w0.305: C314.1 17.65,12.26 ; C314.1 17.12,12.76 ; C314.1 16.58,12.26 ; 18.51,12.76 C316.1 17.98,12.26
  vias: v1(17.24,13.03) v1(18.26,13.03)
-3V3_A: length 94.1
  TOP w0.305: 47.52,38.55 C221.1 47.02,38.02 ; 12.47,11.31 C323.2 ; C323.2 12.93,11.72 ; C323.2 13.38,11.31 ; v1(56.28,28.78) 56.07,28.57 A11.4 54.51,28.57 53.88,27.95 A11.PAD ; 11.91,11.72 C319.2 12.37,11.31 ; 13.56,11.63 A12.2
  TOP w0.508: E19.2 40.64,20.62 ; E19.2 40.64,19.4 ; E19.2 40.09,20.01 ; 48.13,38.45 E22.1 48.74,37.91 ; 38.76,20.2 C222.1 39.75,21.66 E24.1
  L6_SIG w0.635: v1(11.91,11.88) v1(13.05,11.88) 15.09,13.92 19.59,13.92 20.23,13.28 31.79,13.28 33.12,14.62 33.12,16.08 33.75,16.71 35.66,16.71 v1(38.96,20.01) v1(39.6,20.01)
  BOTTOM w0.254: v1(13.05,11.88) 13.18,12.01 13.82,12.01 16.61,14.81 R129.2
  BOTTOM w0.305: 11.68,11.18 C315.2 11.15,11.68 ; 12.14,11.18 C317.2 ; C317.2 13.21,11.18 ; C317.2 12.67,11.68 ; v1(56.28,28.78) C309.2 C307.2 54.9,29.41
  BOTTOM w0.508: 50.2,30.68 50.2,36.14 48.55,37.79 v1(47.72,37.79) v1(47.09,37.79) ; 50.2,30.68 48.49,28.97 48.49,22.1 46.02,19.63 43.74,19.63 43.1,20.27 UNK-3V3_A.1 40.49,20.01 v1(39.6,20.01) v1(38.96,20.01) ; 50.2,30.68 53.63,30.68 54.9,29.41
-3V3_AWG_A: length 7.7
  TOP w0.305: C247.2 C251.2 ; C247.2 40.4,27 ; C247.2 C254.2 40.4,27.76 ; C251.2 40.4,26.24 ; C251.2 40.8,25.78 ; C245.2 41.19,25.56 ; C245.2 41.19,24.53 41.06,24.39 ; C245.2 40.69,25.03
  TOP w0.508: C243.2 40.8,21.83 E24.2
  TOP w0.635: A10.4 39.9,26.74
  TOP w0.762: C243.2 40.8,24.01
-3V3_SC_A: length 38.8
  TOP w0.254: U4.21 45.05,44.39 v1(44.8,44.14) 44.55,44.39 U4.22 ; U3.21 45.05,56.33 v1(44.8,56.08) 44.55,56.33 U3.22 ; U4.16 45.94,43.5 v1(45.69,43.25) 45.94,43 U4.15 ; U3.16 45.94,55.44 v1(45.69,55.19) 45.94,54.94 U3.15
  TOP w0.305: U4.16 47.55,43.5 ; 48.4,53.79 C110.2 ; C110.2 48.8,53.34 ; C110.2 48.8,54.25 ; 48.4,42.49 C165.2 ; C165.2 48.8,42.95 ; C165.2 C167.2 ; 46.58,59.17 C114.2 46.12,59.57 ; U3.15 47.55,54.94 ; 48.4,52.52 C112.2 ; C112.2 48.8,52.07 ; C112.2 48.8,52.98 ; 44.55,47.23 C171.2 45.01,47.64 ; 48.8,41.27 C167.2 ; C167.2 48.4,41.73 ; 46.12,47.64 C161.2 ; C161.2 47.04,47.64 ; C161.2 46.58,47.23 ; 44.55,46.82 U4.22 ; 45.05,46.42 U4.21 ; 48.4,43.51 C169.2 48.8,43.05 ; 45.11,47.64 C159.2 ; C159.2 45.57,47.23 ; C159.2 46.02,47.64 ; 48.4,55.06 C118.2 48.8,54.61 ; 45.05,58.36 U3.21 ; 45.01,59.57 C120.2 44.55,59.17 ; U3.16 47.55,55.44 ; 45.11,59.57 C116.2 ; C116.2 46.02,59.57 ; C116.2 45.57,59.17 ; 44.55,58.76 U3.22 ; U4.15 47.55,43
  TOP w0.508: 48.13,39.42 E22.2 48.74,39.96
  BOTTOM w0.305: 45.36,59.76 C108.2 44.86,59.23 ; 46.77,47.13 C155.2 46.14,47.83 ; 46.65,59.19 C106.2 46.01,59.89 ; R131.2 48.23,41.78 v1(48.23,41.98) ; 45.48,47.83 C157.2 44.99,47.29
  vias: v1(43.91,56.08) v1(43.91,55.19) v1(43.91,54.3) v1(43.91,44.14) v1(43.91,43.25) v1(43.91,42.36) v1(44.36,55.64) v1(44.36,54.75) v1(44.36,43.7) v1(44.36,42.81) v1(44.8,58.87) v1(44.8,55.19) v1(44.8,54.3) v1(44.8,43.25) v1(44.8,42.36) v1(45.06,46.94) v1(45.25,55.64) v1(45.25,54.75) v1(45.25,43.7) v1(45.25,42.81) v1(45.44,58.87) v1(45.69,56.08) v1(45.69,54.3) v1(45.69,44.14) v1(45.69,42.36) v1(46.07,58.87) v1(46.58,46.94) v1(47.34,51.76) v1(48.11,51.76) v1(48.23,42.75)
-5V0_SC_A: length 12.5
  TOP w0.305: C151.1 38.39,43.5 C148.1 ; C151.1 C153.1 ; C151.1 37.98,42.49 ; C153.1 38.39,41.02 ; C153.1 37.98,41.48 ; C148.1 38.4,42.97 ; C148.1 37.9,43.51 ; 14.86,51.23 E5.2 15.47,51.78 ; C100.1 38.39,54.56 38.52,54.68 38.52,55.12 C98.1 38.12,55.26 ; C100.1 C102.1 ; C100.1 37.98,54.43 ; 38.39,52.96 C102.1 ; C102.1 37.98,53.41
  BOTTOM w0.305: C329.1 15.35,52.6 ; C329.1 14.8,52.02 ; C329.1 15.35,51.43 ; 14.42,50.43 VR1.5 15.44,50.94
  vias: v1(14.58,52.27) v1(14.58,51.64) v1(37.69,55.45) v1(37.69,54.81) v2(37.82,43.51) v2(37.82,42.87)
-6V0_A: length 33
  TOP w0.305: 43.83,17.23 U13.4 43.12,16.82 ; U13.8 46.23,19.14 ; U13.8 45.52,18.73 ; U13.8 46.95,18.73 ; U13.8 U13.7 ; 45.52,18.23 U13.7 ; U13.7 47.09,18.23 ; 47.32,18.42 C217.1 ; C217.1 48.39,18.42 ; C217.1 47.85,18.91
  TOP w0.406: 58.23,10.61 R9.2 58.72,11.12
  TOP w0.889: 54.85,11.88 C9.1 ; C9.1 57.36,11.88 ; C9.1 56.11,12.94 ; 51.8,11.88 C12.1 ; C12.1 53.06,12.94 ; C12.1 54.32,11.88
  TOP w1.016: 58.43,11.67 L4.2 57.66,13.03
  BOTTOM w0.305: 24.74,38.69 E13.1 25.35,38.15 ; 26.98,39.82 C210.1 27.47,39.29 ; 21.92,6.91 21.92,6.3 22.47,6.3 ; 51.41,12.27 51.33,12.34 R10.2 ; 24.92,39.29 C211.1 25.42,39.82 ; 22.6,7.76 C209.1 22.07,7.27
  BOTTOM w0.508: 27.05,38.66 E15.1 26.5,38.05 ; 58.52,12.39 UNK-6V0_A.1 57.76,13.15
  BOTTOM w1.016: C9.1 57.36,11.88 ; C9.1 54.85,11.88 ; C9.1 56.11,12.94 ; C12.1 54.32,11.88 ; C12.1 51.8,11.88 ; C12.1 53.06,12.94
  vias: v1(22.96,7.19) v1(22.96,6.42) v1(25.5,39.06) v1(26.13,39.06) v1(26.77,39.06) v1(47.22,19.76) v1(47.22,19.12) v1(47.85,19.76) v1(47.85,19.12) v1(48.49,19.76) v1(48.49,19.12) v1(51.41,12.9) v1(51.41,12.14) v1(51.41,11.5) v1(54.58,13.03) v1(54.58,12.27) v1(54.58,11.5)
